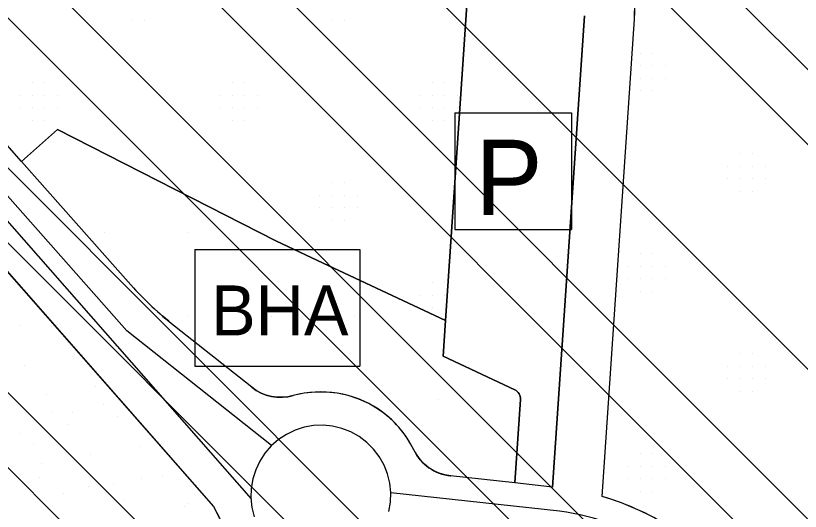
# Model space of a CAD drawing. Extents: x 419109 to 421295, y 4452223 to 4457798.
# Drawn here: x 420824.7 to 421060, y 4455666.6 to 4455815.1 of the extents above; entities that cross this region are included whole.
import ezdxf

# ---------------------------------------------------------------- set-up
doc = ezdxf.new("R2010")
doc.units = 0
for name, color, linetype in [('ADAKENARI', 7, 'Continuous'), ('KALDIRIM_FAT', 7, 'Continuous'), ('PL_AYA_FUAR', 7, 'Continuous'), ('PL_K_BHA', 7, 'Continuous'), ('PL_T_GUNUBIRLIK', 7, 'Continuous'), ('PL_TA_K_OTOPARK', 7, 'Continuous'), ('SEMBOL_FAT', 7, 'Continuous'), ('SN_TR_SIVILASMA', 7, 'Continuous'), ('TRFAT_BHA', 7, 'Continuous'), ('TRFAT_GUNUBİRLİK', 7, 'Continuous'), ('TRFAT_PARKALANI', 7, 'Continuous')]:
    doc.layers.add(name, color=color, linetype=linetype)

msp = doc.modelspace()

# ---------------------------------------------------------------- linework, layer by layer
at = {"layer": 'ADAKENARI'}
for p, q in [((420953.63, 4455723.77), (420963.07, 4455862.75)), ((420985.73, 4455673.85), (420995.32, 4455815.13)), ((421000.57, 4455671.04), (421010.29, 4455814.11)), ((420826.46, 4455771.47), (420807.44, 4455792.93)), ((420837.21, 4455780.99), (420826.46, 4455771.47)), ((420837.21, 4455780.99), (420902.71, 4455747.61)), ((420787.06, 4455778.4), (420884.04, 4455668.02)), ((420859.27, 4455734.42), (420826.46, 4455771.47)), ((420902.71, 4455747.61), (420915.24, 4455741.74)), ((420915.24, 4455741.74), (420953.63, 4455723.77)), ((420895.53, 4455703.77), (420872.37, 4455722.12)), ((420952.9, 4455713.07), (420953.63, 4455723.77)), ((420952.9, 4455713.07), (420974.4, 4455703)), ((420976.12, 4455700.08), (420974.43, 4455675.09)), ((420974.43, 4455675.09), (420955.12, 4455677.19)), ((420985.73, 4455673.85), (420974.43, 4455675.09)), ((420884.04, 4455668.02), (420888.93, 4455658.72))]:
    msp.add_line(p, q, dxfattribs=at)
for centre, radius, start, end in [((420949.68, 4455818.23), 60.75, 356.1141, 62.9933), ((420939.14, 4455806.37), 107.5, 222.0126, 231.5988), ((420904.22, 4455714.74), 14, 231.5988, 285.5206), ((420916.26, 4455671.38), 31, 56.2175, 105.5206), ((420973.13, 4455700.28), 3, 356.1139, 64.9143), ((420916.26, 4455671.38), 31, 26.002, 56.2175), ((420956.71, 4455691.11), 14, 206.002, 263.771), ((420978.36, 4455594.67), 79.53, 56.1721, 73.7808)]:
    msp.add_arc(centre, radius, start, end, dxfattribs=at)
at = {"layer": 'KALDIRIM_FAT'}
for p, q in [((420858.06, 4455720.7), (420799.78, 4455786.5)), ((420794.74, 4455784.81), (420895.3, 4455670.35)), ((420901.48, 4455686.29), (420858.06, 4455720.7)), ((420911.22, 4455691.76), (420908.49, 4455690.89)), ((420914.04, 4455692.26), (420911.22, 4455691.76)), ((420916.91, 4455692.37), (420914.04, 4455692.26)), ((420919.76, 4455692.09), (420916.91, 4455692.37)), ((420922.55, 4455691.42), (420919.76, 4455692.09)), ((420925.22, 4455690.37), (420922.55, 4455691.42)), ((420905.91, 4455689.65), (420903.52, 4455688.07)), ((420908.49, 4455690.89), (420905.91, 4455689.65)), ((420927.72, 4455688.98), (420925.22, 4455690.37)), ((420903.52, 4455688.07), (420901.36, 4455686.18)), ((420930.01, 4455687.25), (420927.72, 4455688.98)), ((420932.04, 4455685.23), (420930.01, 4455687.25)), ((420901.36, 4455686.18), (420899.49, 4455684.01)), ((420933.78, 4455682.96), (420932.04, 4455685.23)), ((420899.49, 4455684.01), (420897.92, 4455681.61)), ((420935.2, 4455680.46), (420933.78, 4455682.96)), ((420897.92, 4455681.61), (420896.7, 4455679.01)), ((420936.26, 4455677.8), (420935.2, 4455680.46)), ((420896.7, 4455679.01), (420895.84, 4455676.28)), ((420936.95, 4455675.02), (420936.26, 4455677.8)), ((420895.84, 4455676.28), (420895.37, 4455673.45)), ((420937.25, 4455672.17), (420936.95, 4455675.02)), ((420895.37, 4455673.45), (420895.28, 4455670.59)), ((420895.28, 4455670.59), (420895.58, 4455667.74)), ((420937.16, 4455669.3), (420937.25, 4455672.17)), ((420987.8, 4455666.58), (420937.25, 4455672.1)), ((420936.68, 4455666.48), (420937.16, 4455669.3)), ((420895.58, 4455667.74), (420896.27, 4455664.96))]:
    msp.add_line(p, q, dxfattribs=at)
msp.add_arc((420978.36, 4455594.67), 72.53, 56.1721, 82.5187, dxfattribs=at)
at = {"layer": 'PL_AYA_FUAR'}
msp.add_lwpolyline([(420787.06, 4455778.4), (420884.04, 4455668.02), (420888.93, 4455658.72), (420890.16, 4455653.06), (420890.46, 4455645.54), (420886.58, 4455581.52), (420884.98, 4455552.19), (420718.56, 4455563.04)], dxfattribs=at)
at = {"layer": 'PL_K_BHA'}
msp.add_lwpolyline([(420907.97, 4455701.25), (420906.36, 4455700.9), (420904.72, 4455700.75), (420903.08, 4455700.78), (420901.45, 4455701.02), (420899.85, 4455701.44), (420898.32, 4455702.04), (420896.87, 4455702.82), (420895.53, 4455703.77), (420895.53, 4455703.77), (420872.37, 4455722.12), (420872.37, 4455722.12), (420870.62, 4455723.54), (420868.9, 4455724.99), (420867.21, 4455726.48), (420865.56, 4455728), (420863.94, 4455729.55), (420862.35, 4455731.14), (420860.79, 4455732.77), (420859.27, 4455734.42), (420859.27, 4455734.42), (420826.46, 4455771.47), (420837.21, 4455780.99), (420902.71, 4455747.61), (420915.24, 4455741.74), (420953.63, 4455723.77), (420952.9, 4455713.07), (420974.4, 4455703), (420974.4, 4455703), (420974.79, 4455702.78), (420975.15, 4455702.5), (420975.46, 4455702.18), (420975.71, 4455701.81), (420975.91, 4455701.4), (420976.05, 4455700.98), (420976.12, 4455700.53), (420976.12, 4455700.08), (420976.12, 4455700.08), (420974.43, 4455675.09), (420955.12, 4455677.19), (420955.19, 4455677.19), (420953.45, 4455677.49), (420951.77, 4455678.01), (420950.16, 4455678.73), (420948.66, 4455679.65), (420947.28, 4455680.76), (420946.05, 4455682.02), (420945, 4455683.44), (420944.13, 4455684.97), (420944.13, 4455684.97), (420943.17, 4455686.78), (420942.1, 4455688.51), (420940.91, 4455690.18), (420939.62, 4455691.76), (420938.23, 4455693.26), (420936.74, 4455694.66), (420935.16, 4455695.95), (420933.5, 4455697.14), (420933.5, 4455697.14), (420930.64, 4455698.85), (420927.6, 4455700.23), (420924.44, 4455701.28), (420921.18, 4455701.99), (420917.87, 4455702.34), (420914.54, 4455702.33), (420911.22, 4455701.97), (420907.97, 4455701.25)], close=True, dxfattribs=at)
at = {"layer": 'PL_T_GUNUBIRLIK'}
for points in [[(420861.6, 4455971.18), (420864.37, 4455963.22), (420867.53, 4455955.4), (420871.07, 4455947.75), (420874.98, 4455940.29), (420879.26, 4455933.02), (420883.89, 4455925.98), (420888.86, 4455919.17), (420894.16, 4455912.62), (420899.78, 4455906.33), (420905.7, 4455900.33), (420911.91, 4455894.63), (420918.4, 4455889.24), (420925.14, 4455884.18), (420932.12, 4455879.46), (420939.33, 4455875.09), (420946.74, 4455871.07), (420963.07, 4455862.75), (420953.63, 4455723.77), (420915.24, 4455741.74), (420902.71, 4455747.61), (420837.21, 4455780.99), (420826.46, 4455771.47), (420807.44, 4455792.93)], [(421014.74, 4455665.39), (421012, 4455666.74), (421009.21, 4455667.97), (421006.37, 4455669.11), (421003.49, 4455670.13), (421000.57, 4455671.04), (421010.29, 4455814.11), (421010.42, 4455819.17)]]:
    msp.add_lwpolyline(points, dxfattribs=at)
at = {"layer": 'PL_TA_K_OTOPARK'}
msp.add_lwpolyline([(420995.32, 4455815.13), (420985.73, 4455673.85), (420974.43, 4455675.09), (420976.12, 4455700.08), (420976.12, 4455700.08), (420976.12, 4455700.53), (420976.05, 4455700.98), (420975.91, 4455701.4), (420975.71, 4455701.81), (420975.46, 4455702.18), (420975.15, 4455702.5), (420974.79, 4455702.78), (420974.4, 4455703), (420974.4, 4455703), (420952.9, 4455713.07), (420953.63, 4455723.77), (420963.07, 4455862.75)], dxfattribs=at)
at = {"layer": 'SEMBOL_FAT'}
for p, q in [((420956.45, 4455786.01), (420956.45, 4455751.01)), ((420956.45, 4455786.01), (420991.45, 4455786.01)), ((420991.45, 4455786.01), (420991.45, 4455751.01)), ((420956.45, 4455751.01), (420991.45, 4455751.01)), ((420878.42, 4455745.06), (420878.42, 4455710.06)), ((420878.42, 4455745.06), (420927.89, 4455745.06)), ((420927.89, 4455745.06), (420927.89, 4455710.06)), ((420878.42, 4455710.06), (420927.89, 4455710.06))]:
    msp.add_line(p, q, dxfattribs=at)
at = {"layer": 'SN_TR_SIVILASMA'}
for p, q in [((421272.55, 4455588.71), (420264.03, 4456597.24)), ((421272.32, 4455566.5), (420257.91, 4456580.91)), ((421271.63, 4455499.84), (420239.54, 4456531.93)), ((421271.16, 4455455.4), (420227.3, 4456499.27)), ((421270.93, 4455433.18), (420221.05, 4456483.06)), ((421270.47, 4455388.74), (420206.08, 4456453.13)), ((421270.24, 4455366.53), (420198.6, 4456438.16)), ((421269.77, 4455322.09), (420183.63, 4456408.23)), ((421269.54, 4455299.87), (420176.15, 4456393.26)), ((421269.08, 4455255.43), (420161.18, 4456363.33)), ((421268.85, 4455233.21), (420151.38, 4456350.68))]:
    msp.add_line(p, q, dxfattribs=at)
at = {"layer": 'TRFAT_BHA'}
for p, q in [((420851.46, 4455750.09), (420851.46, 4455750.09)), ((420876.46, 4455750.09), (420876.46, 4455750.09)), ((420876.46, 4455725.09), (420876.46, 4455725.09)), ((420901.46, 4455725.09), (420901.46, 4455725.09)), ((420926.46, 4455725.09), (420926.46, 4455725.09)), ((420951.46, 4455700.09), (420951.46, 4455700.09))]:
    msp.add_line(p, q, dxfattribs=at)
at = {"layer": 'TRFAT_GUNUBİRLİK'}
for p, q in [((420859.7, 4455813.77), (420859.7, 4455813.77)), ((420863.45, 4455813.77), (420863.45, 4455813.77)), ((420919.7, 4455813.77), (420919.7, 4455813.77)), ((420923.45, 4455813.77), (420923.45, 4455813.77)), ((421012.1, 4455803.82), (421012.1, 4455803.82)), ((421015.85, 4455803.82), (421015.85, 4455803.82)), ((421012.1, 4455800.07), (421012.1, 4455800.07)), ((421015.85, 4455800.07), (421015.85, 4455800.07)), ((421019.6, 4455800.07), (421019.6, 4455800.07)), ((420829.7, 4455795.02), (420829.7, 4455795.02)), ((420833.45, 4455795.02), (420833.45, 4455795.02)), ((420889.7, 4455795.02), (420889.7, 4455795.02)), ((420893.45, 4455795.02), (420893.45, 4455795.02)), ((420949.7, 4455795.02), (420949.7, 4455795.02)), ((420953.45, 4455795.02), (420953.45, 4455795.02)), ((421012.1, 4455796.32), (421012.1, 4455796.32)), ((421015.85, 4455796.32), (421015.85, 4455796.32)), ((421019.6, 4455796.32), (421019.6, 4455796.32)), ((421012.1, 4455792.57), (421012.1, 4455792.57)), ((421015.85, 4455792.57), (421015.85, 4455792.57)), ((420825.95, 4455791.27), (420825.95, 4455791.27)), ((420829.7, 4455791.27), (420829.7, 4455791.27)), ((420833.45, 4455791.27), (420833.45, 4455791.27)), ((420837.2, 4455791.27), (420837.2, 4455791.27)), ((420885.95, 4455791.27), (420885.95, 4455791.27)), ((420889.7, 4455791.27), (420889.7, 4455791.27)), ((420893.45, 4455791.27), (420893.45, 4455791.27)), ((420897.2, 4455791.27), (420897.2, 4455791.27)), ((420945.95, 4455791.27), (420945.95, 4455791.27)), ((420949.7, 4455791.27), (420949.7, 4455791.27)), ((420953.45, 4455791.27), (420953.45, 4455791.27)), ((420957.2, 4455791.27), (420957.2, 4455791.27)), ((420825.95, 4455787.52), (420825.95, 4455787.52)), ((420829.7, 4455787.52), (420829.7, 4455787.52)), ((420833.45, 4455787.52), (420833.45, 4455787.52)), ((420837.2, 4455787.52), (420837.2, 4455787.52)), ((420885.95, 4455787.52), (420885.95, 4455787.52)), ((420889.7, 4455787.52), (420889.7, 4455787.52)), ((420893.45, 4455787.52), (420893.45, 4455787.52)), ((420897.2, 4455787.52), (420897.2, 4455787.52)), ((420945.95, 4455787.52), (420945.95, 4455787.52)), ((420949.7, 4455787.52), (420949.7, 4455787.52)), ((420953.45, 4455787.52), (420953.45, 4455787.52)), ((420957.2, 4455787.52), (420957.2, 4455787.52)), ((420829.7, 4455783.77), (420829.7, 4455783.77)), ((420833.45, 4455783.77), (420833.45, 4455783.77)), ((420889.7, 4455783.77), (420889.7, 4455783.77)), ((420893.45, 4455783.77), (420893.45, 4455783.77)), ((420949.7, 4455783.77), (420949.7, 4455783.77)), ((420953.45, 4455783.77), (420953.45, 4455783.77)), ((421042.1, 4455773.82), (421042.1, 4455773.82)), ((421045.85, 4455773.82), (421045.85, 4455773.82)), ((421038.35, 4455770.07), (421038.35, 4455770.07)), ((421042.1, 4455770.07), (421042.1, 4455770.07)), ((421045.85, 4455770.07), (421045.85, 4455770.07)), ((421049.6, 4455770.07), (421049.6, 4455770.07)), ((420919.7, 4455765.02), (420919.7, 4455765.02)), ((420923.45, 4455765.02), (420923.45, 4455765.02)), ((421038.35, 4455766.32), (421038.35, 4455766.32)), ((421042.1, 4455766.32), (421042.1, 4455766.32)), ((421045.85, 4455766.32), (421045.85, 4455766.32)), ((421049.6, 4455766.32), (421049.6, 4455766.32)), ((421042.1, 4455762.57), (421042.1, 4455762.57)), ((421045.85, 4455762.57), (421045.85, 4455762.57)), ((420915.95, 4455761.27), (420915.95, 4455761.27)), ((420919.7, 4455761.27), (420919.7, 4455761.27)), ((420923.45, 4455761.27), (420923.45, 4455761.27)), ((420927.2, 4455761.27), (420927.2, 4455761.27)), ((420915.95, 4455757.52), (420915.95, 4455757.52)), ((420919.7, 4455757.52), (420919.7, 4455757.52)), ((420923.45, 4455757.52), (420923.45, 4455757.52)), ((420927.2, 4455757.52), (420927.2, 4455757.52)), ((420919.7, 4455753.77), (420919.7, 4455753.77)), ((420923.45, 4455753.77), (420923.45, 4455753.77)), ((421012.1, 4455743.82), (421012.1, 4455743.82)), ((421015.85, 4455743.82), (421015.85, 4455743.82)), ((421008.35, 4455740.07), (421008.35, 4455740.07)), ((421012.1, 4455740.07), (421012.1, 4455740.07)), ((421015.85, 4455740.07), (421015.85, 4455740.07)), ((421019.6, 4455740.07), (421019.6, 4455740.07)), ((421008.35, 4455736.32), (421008.35, 4455736.32)), ((421012.1, 4455736.32), (421012.1, 4455736.32)), ((421015.85, 4455736.32), (421015.85, 4455736.32)), ((421019.6, 4455736.32), (421019.6, 4455736.32)), ((420949.7, 4455735.02), (420949.7, 4455735.02)), ((420953.45, 4455735.02), (420953.45, 4455735.02)), ((421012.1, 4455732.57), (421012.1, 4455732.57)), ((421015.85, 4455732.57), (421015.85, 4455732.57)), ((420945.95, 4455731.27), (420945.95, 4455731.27)), ((420949.7, 4455731.27), (420949.7, 4455731.27)), ((420953.45, 4455731.27), (420953.45, 4455731.27)), ((420945.95, 4455727.52), (420945.95, 4455727.52)), ((420949.7, 4455727.52), (420949.7, 4455727.52)), ((420953.45, 4455727.52), (420953.45, 4455727.52)), ((421042.1, 4455713.82), (421042.1, 4455713.82)), ((421045.85, 4455713.82), (421045.85, 4455713.82)), ((421038.35, 4455710.07), (421038.35, 4455710.07)), ((421042.1, 4455710.07), (421042.1, 4455710.07)), ((421045.85, 4455710.07), (421045.85, 4455710.07)), ((421049.6, 4455710.07), (421049.6, 4455710.07)), ((421038.35, 4455706.32), (421038.35, 4455706.32)), ((421042.1, 4455706.32), (421042.1, 4455706.32)), ((421045.85, 4455706.32), (421045.85, 4455706.32)), ((421049.6, 4455706.32), (421049.6, 4455706.32)), ((421042.1, 4455702.57), (421042.1, 4455702.57)), ((421045.85, 4455702.57), (421045.85, 4455702.57)), ((421012.1, 4455683.82), (421012.1, 4455683.82)), ((421015.85, 4455683.82), (421015.85, 4455683.82)), ((421008.35, 4455680.07), (421008.35, 4455680.07)), ((421012.1, 4455680.07), (421012.1, 4455680.07)), ((421015.85, 4455680.07), (421015.85, 4455680.07)), ((421019.6, 4455680.07), (421019.6, 4455680.07)), ((421008.35, 4455676.32), (421008.35, 4455676.32)), ((421012.1, 4455676.32), (421012.1, 4455676.32)), ((421015.85, 4455676.32), (421015.85, 4455676.32)), ((421019.6, 4455676.32), (421019.6, 4455676.32)), ((421012.1, 4455672.57), (421012.1, 4455672.57)), ((421015.85, 4455672.57), (421015.85, 4455672.57))]:
    msp.add_line(p, q, dxfattribs=at)
at = {"layer": 'TRFAT_PARKALANI'}
for p, q in [((420826.2, 4455722.37), (420826.2, 4455722.37)), ((420835.39, 4455722.02), (420835.39, 4455722.02)), ((420842.05, 4455713.04), (420842.05, 4455713.04)), ((420827.28, 4455710.43), (420827.28, 4455710.43)), ((420848.71, 4455704.06), (420848.71, 4455704.06)), ((420833.94, 4455701.45), (420833.94, 4455701.45)), ((420851.03, 4455698.73), (420851.03, 4455698.73)), ((420835.39, 4455696.41), (420835.39, 4455696.41)), ((420841.65, 4455696.17), (420841.65, 4455696.17)), ((420855.37, 4455695.08), (420855.37, 4455695.08)), ((420840.6, 4455692.47), (420840.6, 4455692.47)), ((420825.83, 4455689.87), (420825.83, 4455689.87)), ((420830.16, 4455686.53), (420830.16, 4455686.53)), ((420862.03, 4455686.1), (420862.03, 4455686.1)), ((420847.26, 4455683.49), (420847.26, 4455683.49)), ((420832.49, 4455680.89), (420832.49, 4455680.89)), ((420831.92, 4455676.71), (420831.92, 4455676.71)), ((420862.33, 4455676.43), (420862.33, 4455676.43)), ((420868.69, 4455677.12), (420868.69, 4455677.12)), ((420846.69, 4455674.11), (420846.69, 4455674.11)), ((420853.92, 4455674.51), (420853.92, 4455674.51)), ((420839.15, 4455671.91), (420839.15, 4455671.91)), ((420857.1, 4455669.98), (420857.1, 4455669.98)), ((420875.35, 4455668.14), (420875.35, 4455668.14)), ((420876.24, 4455668.9), (420876.24, 4455668.9))]:
    msp.add_line(p, q, dxfattribs=at)

# ---------------------------------------------------------------- texts
at = {"layer": 'SEMBOL_FAT'}
for s, height, p in [('P', 22.5, (420962.65, 4455755.44)), ('BHA', 15, (420883.31, 4455719.29))]:
    msp.add_text(s, height=height, dxfattribs=at).set_placement(p)

doc.saveas('drawing.dxf')
